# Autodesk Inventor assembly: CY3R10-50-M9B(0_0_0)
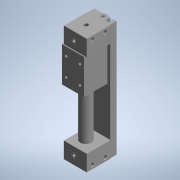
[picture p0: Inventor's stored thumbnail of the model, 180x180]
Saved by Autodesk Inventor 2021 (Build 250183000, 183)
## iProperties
Part Number: CY3R10-50-M9B(0_0_0)
Catalog Web Link: www.cadenas.de
Description: CY3R-Magnetically Coupled Rodless Cylinder Direct Mount Type
Vendor: SMC
Document SubType Name: Assembly
Designer: partserver
Manufacturer: SMC
Mass: 70.5141 g
Surface Area: 261.566 cm^2
Volume: 70.5141 cm^3
Density: 1 g/cm^3
Category: PARTsolutions
Company: SMC
PSOL_IDENT_0: {$CADENAS_DATA\23d-libs\smc_jp\actuator\rodless_cylinders\cy3\cy3r_asmtab.prj},266 {VTYP=3D},{STYP=A
PSOL_IDENT_1: SSTAB},{NB=CY3R10-50-M9B(0_0_0)},{LINA=CY3R10-50-M9B},{NN=CY3R},{DATE=12.02.2021 08:48:25},{GEOMDATE=
PSOL_IDENT_2: 14.07.2020 03:32:41},{VERSION=},{LINEID=20},{WBVAR=PIPING,THREAD1,STROKE,POS,STOP,RAIL,AUTOSWITCH,LE
PSOL_IDENT_3: AD,NUMBER,OMSC,THREAD2},{WBNUMERIC=STROKE,POS}  {NB=CY3R10-50-M9B(0_0_0)},{LINA=CY3R10-50-M9B},{KT=D
PSOL_IDENT_4: UMMY},{PIPING=},{PIPINGX='','(-) Standard type','G','(G) Centralized piping type'},{DI=1},{BORE=10},
PSOL_IDENT_5: {THREAD1=},{THREAD1X='','(-) M thread'},{STROKE=50},{STROKEX=50,100,150,200,250,300},{STDSTROKE=50,1
PSOL_IDENT_6: 00,150,200,250,300},{POS=0},{STOP=0},{COM=-},{RAIL=},{RALLX='', '(-) With switch rail', 'N', '(N) Wi
PSOL_IDENT_7: thout switch rail'},{AUTOSWITCH=-M9B},{AUTOSWITCHX='','(-) Without autoswitch (Built-in magnet)','-A
PSOL_IDENT_8: 90','A90','-A93','A93','-A96','A96','-M9N','M9N','-M9P','M9P','-M9B','M9B','-M9NW','M9NW','-M9PW','M
PSOL_IDENT_9: 9PW','-M9BW','M9BW','-M9NA','M9NA','-M9PA','M9PA','-M9BA','M9BA'},{LEAD=},{LEADX='','(-) 0.5 m','M','
PSOL_IDENT_10: (M) 1 m','L','(L) 3 m','Z','(Z) 5 m'},{NUMBER=},{NUMBERX='','(-) 2 Pcs','S','(S) 1 Pcs'},{OMSC=},{OM
PSOL_IDENT_11: SCX= '','(-) None','-XC57','(XC57) With floating joint'},{THREAD2=0},{SMIN1=25},{SMIN2=50},{SMAX1=50
PSOL_IDENT_12: 0},{SMAX2=500},{ORDER=CY3R10-50-M9B},{A=9.0},{B=6.5},{C=3.2},{CB=2},{CR=0.5},{D=12.0},{F=6.5},{G=4.0
PSOL_IDENT_13: },{GP=27},{GW=25.5},{H=26},{HA=24},{HB=14.0},{HC=25},{HP=14.0},{HP1=14.0},{HP2=0.0},{HR=24},{HS=5.0}
PSOL_IDENT_14: ,{HT=14.0},{HT1=14.0},{HT2=0.0},{JXE=M4x0.7x6},{K=9},{L=38},{LD=3.5},{M=4.0},{MM=M3x0.5},{N=4.5},{PW=
PSOL_IDENT_15: 26},{Q=68},{QW=14},{T=17.5},{TC=14.0},{W=20},{WP=13.0},{WS=8},{X=15},{Y=39.5},{Z=76},{P=M5x0.8},{PTN=
PSOL_IDENT_16: -},{PTF=-},{PPATH=cy3r/assembly/cy3r_asmsbl.prj},{MODEL=CY3R10-50-M9B},{NENN=CY3R10}
NB: CY3R10-50-M9B(0_0_0)
NN: CY3R
NT: Magnetically Coupled Rodless Cylinder Direct Mount Type
NBSYN: $ORDER.($POS._$STOP._$THREAD2.)
LINA: CY3R10-50-M9B
CATALOG: SMC (JP
ROWDESC: CY3R10
PIPING: (-) Standard type
BORE: 10
THREAD1: (-) M thread
STROKE: 50
POS: 0
STOP: Standard stroke
COM: -
RAIL: (-) With switch rail
AUTOSWITCH: M9B Solid state-General-Grommet-Indicator light:Yes-2 wire-In line
LEAD: (-) 0.5 m
NUMBER: (-) 2 Pcs
OMSC: (-) None
THREAD2: on
SUPPLIER: SMC
ARTICLENO: CY3R10-50-M9B(0_0_0)
BOMINFO: CY3R10-50-M9B
CREATOR: CADENAS GmbH
Title: CY3R10-50-M9B
Author: Cadenas PARTsolutions
Comments: Magnetically Coupled Rodless Cylinder Direct Mount Type
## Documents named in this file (4)
- D:\01 Paralaia\Grupos de Traballo\GT Maquetas\CAD 3D\E_Medida\CY3R10-50-M9B\CY3R10-50-M9B(0_0_0).iam
- D:\01 Paralaia\Grupos de Traballo\GT Maquetas\CAD 3D\E_Medida\CY3R10-50-M9B\CY3R10-50-M9B(0)_CT.ipt
- D:\01 Paralaia\Grupos de Traballo\GT Maquetas\CAD 3D\E_Medida\CY3R10-50-M9B\CY3R10(0)_BODY.ipt
- D:\01 Paralaia\Grupos de Traballo\GT Maquetas\CAD 3D\E_Medida\CY3R10-50-M9B\CY3R-M9B_SW.ipt
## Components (4 placed, 3 different names)
1. CY3R10-50-M9B(0)_CT:1 — Insertar:1, Ángulo:1, Insertar:2
2. CY3R10(0)_BODY:1 — Insertar:1, Ángulo:1, Insertar:2
3. CY3R-M9B_SW:1
4. CY3R-M9B_SW:2
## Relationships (3: Insert 2, Angle 1)
- Insertar:1: CY3R10-50-M9B(0)_CT:1 ↔ CY3R10(0)_BODY:1
- Ángulo:1 [Angle]: CY3R10-50-M9B(0)_CT:1 ↔ CY3R10(0)_BODY:1
- Insertar:2: CY3R10-50-M9B(0)_CT:1 ↔ CY3R10(0)_BODY:1
